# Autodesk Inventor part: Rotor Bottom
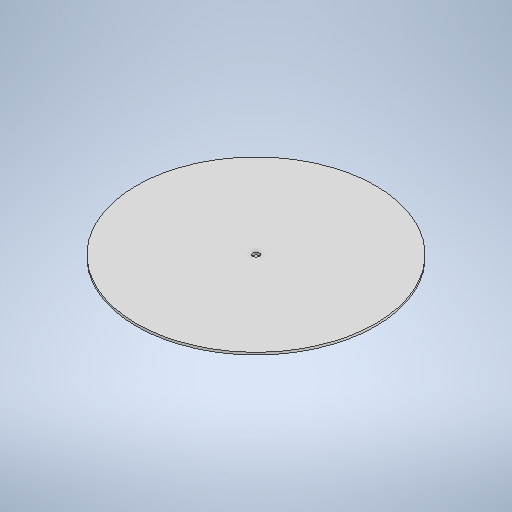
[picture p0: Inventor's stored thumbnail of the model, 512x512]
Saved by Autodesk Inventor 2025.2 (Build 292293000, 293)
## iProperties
Created: 2025-05
Part Number: Rotor Bottom
Material: Generic
Document SubType Name: Modeling
Designer: bensa
Density: 1 g/cm^3
Appearance: Default
Author: bensa
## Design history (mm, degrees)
sketch "Sketch1"
  geometry: C1 r 150 at (0, 0); 1 further point
  constraints: 1 centre point, 1 coincident
  dimensions: "d0" = 300 diameter of C1
extrude "Extrusion1" new body sketch "Sketch1" distance "d1" = 3; taper "d2" = 0 deg
sketch "Sketch6"
  geometry: C1 r 4 at (0, 0); 1 further point
  constraints: 1 centre point, 1 coincident
  dimensions: "d16" = 8 diameter of C1
extrude "Extrusion6" cut sketch "Sketch6" distance "d17" = 10; taper "d18" = 0 deg
body "Solid1"
